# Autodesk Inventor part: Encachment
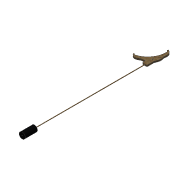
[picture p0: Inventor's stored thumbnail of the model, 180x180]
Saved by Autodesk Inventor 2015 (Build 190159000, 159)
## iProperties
Created: 2015-01
Part Number: Encachment
Material: Generic
Document SubType Name: Modeling
Designer: Steve Brooks
Density: 1 g/cm^3
Appearance: IDS MDF
Author: Steve Brooks
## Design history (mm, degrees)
sketch "Sketch1"
  geometry: L1 (119.651, 64.824)-(119.651, 64.835); L2 (121.47, 181.895)-(113.871, 187.407); L3 (113.871, 187.407)-(119.551, 195.23); L4 (119.551, 195.23)-(133.119, 185.365); L5 (138.468, 49.754)-(138.468, 3.892); L6 (133.394, -1.188)-(105.489, -1.209); L7 (100.409, 3.871)-(100.409, 19.045); L8 (-0.41, 29.779)-(1.334, 30.298); L9 (1.334, 30.298)-(6.729, 27.768); L10 (6.729, 27.768)-(9.777, 25.553); A1 r 38.07 centre (110.741, 154.566) between (148.766, 152.705) and (133.119, 185.365); A2 r 170.463 centre (-21.49, 161.105) between (147.085, 135.804) and (148.766, 152.705); A3 r 31.774 centre (178.508, 131.089) between (147.085, 135.804) and (148.024, 122.124); A4 r 75.173 centre (75.905, 100.916) between (142.472, 65.99) and (148.024, 122.124); A5 r 34.925 centre (173.394, 49.754) between (142.472, 65.99) and (138.468, 49.754); A6 r 5.071 centre (133.397, 3.883) between (133.394, -1.188) and (138.468, 3.892); A7 r 5.08 centre (105.489, 3.871) between (100.409, 3.871) and (105.489, -1.209); A8 r 5.08 centre (95.329, 19.045) between (100.409, 19.045) and (93.871, 23.912); A9 r 75.248 centre (72.294, 96) between (75.675, 20.828) and (93.871, 23.912); A10 r 31.767 centre (77.109, -10.907) between (75.675, 20.828) and (61.415, 16.713); A11 r 174.455 centre (-24.743, 168.408) between (42.945, 7.619) and (61.415, 16.713); A12 r 31.746 centre (30.627, 36.879) between (0.406, 27.159) and (42.945, 7.619); A13 r 97.981 centre (93.538, 57.596) between (-0.41, 29.779) and (0.406, 27.159); A14 r 12.511 centre (17.218, 35.61) between (9.777, 25.553) and (21.029, 23.694); A15 r 151.311 centre (-24.557, 167.975) between (21.029, 23.694) and (126.702, 171.948); A16 r 12.689 centre (114.017, 171.626) between (126.702, 171.948) and (121.47, 181.895); 2 further points; 1 other entity
  constraints: 32 point on circle, 20 end point, 16 centre point, 2 other
extrude "Extrusion1" new body sketch "Sketch1" distance "d0" = 12; taper "d1" = 0 deg
sketch "Sketch2"
  geometry: L1 (-27.904, 12)-(0, 12) reference; L2 (-27.904, 0)-(-27.904, 12) reference; C1 r 3 at (-13.952, 6); 3 further points
  constraints: 2 midpoint, 1 centre point, 1 horizontal alignment, 1 vertical alignment
  dimensions: "d2" = 6 diameter of C1
extrude "Extrusion2" join sketch "Sketch2" distance "d3" = 900; taper "d4" = 0 deg
sketch "Sketch3"
  geometry: C1 r 3 at (0, 0) reference; C2 r 25 at (0, 0); 1 further point
  constraints: 1 centre point, 1 coincident
  dimensions: "d5" = 50 diameter of C2
extrude "Extrusion3" join sketch "Sketch3" distance "d6" = 100; taper "d7" = 0 deg
sketch "Sketch4"
  geometry: C1 r 0.508 at (119.651, 64.829) reference; C2 r 3 at (119.651, 64.829); 1 further point
  constraints: 1 centre point, 1 coincident
  dimensions: "d8" = 6 diameter of C2
extrude "Extrusion4" cut sketch "Sketch4" stored distance "d9" = 10; taper "d10" = 0 deg
sketch "Sketch5"
  geometry: C1 r 2.5 at (-13.952, 6); 1 further point
  constraints: 1 centre point
  dimensions: "d11" = 5 diameter of C1
extrude "Extrusion5" cut sketch "Sketch5" distance "d12" = 20; taper "d13" = 0 deg
body "Solid1"
